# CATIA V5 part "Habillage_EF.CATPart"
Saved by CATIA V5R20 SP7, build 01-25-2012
Part number: Habillage_EF
Bounding box of the stored display mesh (mm): x -3.9 to 4.6, y -49.071 to 21.5, z -11.449 to 6.495
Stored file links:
  F:\IAO\Catia\Habillage_EF.CATPart
  F:\IAO\Catia\asandre.CATProduct
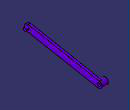
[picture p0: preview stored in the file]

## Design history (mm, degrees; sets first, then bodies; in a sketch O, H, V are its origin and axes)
Set1
  Plane1 "Plan.2,1": linked copy from another document
  Point1 "E": linked copy from another document
  Point2 "F": linked copy from another document
Body1 (main body)
  Sketch1 "Bielle_FE" on Plane1, origin (2.1, 0, 0), H (0, 1, 0), V (0, 0, 1)
    construction line L1 (-46.0959, 3.5462) -> (18.5, -8.5)
    point P1 (-46.0959, 3.5462)
    point P2 (18.5, -8.5)
    line L2 (-45.5459, 6.4954) -> (19.05, -5.5508)
    line L3 (17.95, -11.4492) -> (-46.6458, 0.5971)
    arc A1 centre (18.5, -8.5) radius 3 from (19.05, -5.5508) to (17.95, -11.4492) cw
    arc A2 centre (-46.0959, 3.5462) radius 3 from (-46.6458, 0.5971) to (-45.5459, 6.4954) cw
    reference projected point E1 (-46.0959, 3.5462) from Point1
    reference projected point E2 (18.5, -8.5) from Point2
    circle A3 centre (18.5, -8.5) radius 1.5
    point P7 (18.5, -8.5)
    reference projected point E3 (18.5, -8.5) from Point2
    distance L1 L2 = 3
    radius A3 = 1.5
    tangency: A1 L2, A2 L2, A1 L3, A2 L3
    coincidence: P1 E1, P2 E2, P7 E3
  Pad1 "Bielle_FE": profile Sketch1, direction (-1, 0, 0), length 2
  Sketch2 "Pivot.E" on Plane1, origin (2.1, 0, 0), H (0, 1, 0), V (0, 0, 1)
    circle A1 centre (-46.0959, 3.5462) radius 1.5
    point P1 (-46.0959, 3.5462)
    reference projected point E1 (-46.0959, 3.5462) from Point1
    radius A1 = 1.5
    coincidence: P1 E1
  Pad2 "Pivot.E": profile Sketch2, direction (1, 0, 0), length 2.5
  Sketch3 "Lien.Bielle.FE.Bati" on Plane1, origin (2.1, 0, 0), H (0, 1, 0), V (0, 0, 1)
    circle A1 centre (18.5, -8.5) radius 3
    point P1 (18.5, -8.5)
    reference projected point E1 (18.5, -8.5) from Point2
    circle A2 centre (18.5, -8.5) radius 1.5
    point P2 (18.5, -8.5)
    reference projected point E2 (18.5, -8.5) from Point2
    radius A1 = 3
    radius A2 = 1.5
    coincidence: P1 E1, P2 E2
  Pad3 "Lien.bielle_FE.bati": profile Sketch3, direction (-1, 0, 0), length 6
